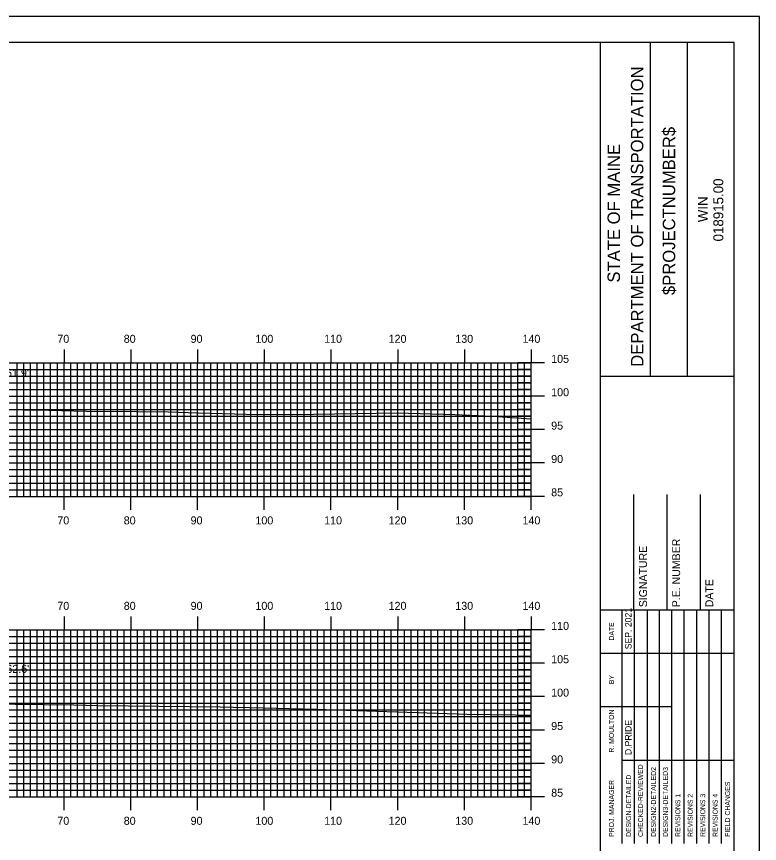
# Model space of a CAD drawing. Extents: x 1775170 to 1775514, y 442591 to 442811.
# Drawn here: x 1775399.1 to 1775510.4, y 442686.7 to 442810.5 of the extents above; entities that cross this region are included whole.
import ezdxf

# ---------------------------------------------------------------- set-up
doc = ezdxf.new("R2010")
doc.units = 0
for name, color, linetype in [('BORDER', 7, 'Continuous'), ('D_Text_Standard', 7, 'Continuous'), ('H_V ANNOTATION', 7, 'Continuous'), ('MAJOR', 7, 'Continuous'), ('MINOR', 7, 'Continuous'), ('PLOT BOUNDARY', 7, 'Continuous'), ('S_Roadway_Centerline', 7, 'Continuous')]:
    doc.layers.add(name, color=color, linetype=linetype)

msp = doc.modelspace()

# ---------------------------------------------------------------- linework, layer by layer
at = {"layer": 'BORDER'}
for p, q in [((1775486.6, 442596.67), (1775486.6, 442806.67)), ((1775494.06, 442756.66), (1775494.06, 442806.66)), ((1775499.65, 442756.66), (1775499.65, 442806.66)), ((1775486.6, 442756.65), (1775506.6, 442756.65)), ((1775491.6, 442721.67), (1775491.6, 442738.97)), ((1775496.6, 442721.67), (1775496.6, 442738.97)), ((1775501.6, 442721.67), (1775501.6, 442738.97)), ((1775486.6, 442721.67), (1775506.6, 442721.67))]:
    msp.add_line(p, q, dxfattribs=at)
msp.add_lwpolyline([(1775186.6, 442596.67), (1775506.6, 442596.67), (1775506.6, 442806.67), (1775186.6, 442806.67)], close=True, dxfattribs=at)
for points in [[(1775489.83, 442715.17), (1775489.83, 442721.67)], [(1775491.69, 442686.68), (1775491.69, 442721.67)], [(1775493.56, 442721.67), (1775493.56, 442686.68)], [(1775495.42, 442686.68), (1775495.42, 442721.67)], [(1775497.28, 442686.68), (1775497.28, 442721.67)], [(1775499.15, 442686.68), (1775499.15, 442721.67)], [(1775501.01, 442686.68), (1775501.01, 442721.67)], [(1775502.87, 442686.68), (1775502.87, 442721.67)], [(1775504.74, 442686.68), (1775504.74, 442721.67)], [(1775489.83, 442686.68), (1775489.83, 442720.26)], [(1775486.6, 442715.17), (1775506.6, 442715.17)], [(1775486.6, 442707.17), (1775489.83, 442707.17)], [(1775489.83, 442707.17), (1775497.28, 442707.17)], [(1775489.83, 442699.17), (1775506.6, 442699.17)]]:
    msp.add_lwpolyline(points, dxfattribs=at)
at = {"layer": 'MAJOR'}
for p, q in [((1775406.2, 442760.67), (1775406.2, 442758.67)), ((1775416.2, 442760.67), (1775416.2, 442758.67)), ((1775426.2, 442760.67), (1775426.2, 442758.67)), ((1775436.2, 442760.67), (1775436.2, 442758.67)), ((1775446.2, 442760.67), (1775446.2, 442758.67)), ((1775456.2, 442760.67), (1775456.2, 442758.67)), ((1775466.2, 442760.67), (1775466.2, 442758.67)), ((1775476.2, 442760.67), (1775476.2, 442758.67)), ((1775196.2, 442758.67), (1775476.2, 442758.67)), ((1775196.2, 442758.67), (1775476.2, 442758.67)), ((1775406.2, 442738.67), (1775406.2, 442758.67)), ((1775416.2, 442738.67), (1775416.2, 442758.67)), ((1775426.2, 442738.67), (1775426.2, 442758.67)), ((1775436.2, 442738.67), (1775436.2, 442758.67)), ((1775446.2, 442738.67), (1775446.2, 442758.67)), ((1775456.2, 442738.67), (1775456.2, 442758.67)), ((1775466.2, 442738.67), (1775466.2, 442758.67)), ((1775478.2, 442758.67), (1775474.19, 442758.67)), ((1775476.2, 442738.67), (1775476.2, 442758.67)), ((1775476.2, 442738.67), (1775476.2, 442758.67)), ((1775196.2, 442753.67), (1775476.2, 442753.67)), ((1775478.2, 442753.67), (1775474.19, 442753.67)), ((1775196.2, 442748.67), (1775476.2, 442748.67)), ((1775478.2, 442748.67), (1775474.19, 442748.67)), ((1775196.2, 442743.67), (1775476.2, 442743.67)), ((1775478.2, 442743.67), (1775474.19, 442743.67)), ((1775196.2, 442738.67), (1775476.2, 442738.67)), ((1775196.2, 442738.67), (1775476.2, 442738.67)), ((1775406.2, 442736.66), (1775406.2, 442738.67)), ((1775416.2, 442736.66), (1775416.2, 442738.67)), ((1775426.2, 442736.66), (1775426.2, 442738.67)), ((1775436.2, 442736.66), (1775436.2, 442738.67)), ((1775446.2, 442736.66), (1775446.2, 442738.67)), ((1775456.2, 442736.66), (1775456.2, 442738.67)), ((1775466.2, 442736.66), (1775466.2, 442738.67)), ((1775478.2, 442738.67), (1775474.19, 442738.67)), ((1775476.2, 442736.66), (1775476.2, 442738.67)), ((1775406.2, 442720.67), (1775406.2, 442718.67)), ((1775416.2, 442720.67), (1775416.2, 442718.67)), ((1775426.2, 442720.67), (1775426.2, 442718.67)), ((1775436.2, 442720.67), (1775436.2, 442718.67)), ((1775446.2, 442720.67), (1775446.2, 442718.67)), ((1775456.2, 442720.67), (1775456.2, 442718.67)), ((1775466.2, 442720.67), (1775466.2, 442718.67)), ((1775476.2, 442720.67), (1775476.2, 442718.67)), ((1775196.2, 442718.67), (1775476.2, 442718.67)), ((1775196.2, 442718.67), (1775476.2, 442718.67)), ((1775406.2, 442693.67), (1775406.2, 442718.67)), ((1775416.2, 442693.67), (1775416.2, 442718.67)), ((1775426.2, 442693.67), (1775426.2, 442718.67)), ((1775436.2, 442693.67), (1775436.2, 442718.67)), ((1775446.2, 442693.67), (1775446.2, 442718.67)), ((1775456.2, 442693.67), (1775456.2, 442718.67)), ((1775466.2, 442693.67), (1775466.2, 442718.67)), ((1775478.2, 442718.67), (1775474.19, 442718.67)), ((1775476.2, 442693.67), (1775476.2, 442718.67)), ((1775476.2, 442693.67), (1775476.2, 442718.67)), ((1775196.2, 442713.67), (1775476.2, 442713.67)), ((1775478.2, 442713.67), (1775474.19, 442713.67)), ((1775196.2, 442708.67), (1775476.2, 442708.67)), ((1775478.2, 442708.67), (1775474.19, 442708.67)), ((1775196.2, 442703.67), (1775476.2, 442703.67)), ((1775478.2, 442703.67), (1775474.19, 442703.67)), ((1775196.2, 442698.67), (1775476.2, 442698.67)), ((1775478.2, 442698.67), (1775474.19, 442698.67)), ((1775196.2, 442693.67), (1775476.2, 442693.67)), ((1775196.2, 442693.67), (1775476.2, 442693.67)), ((1775406.2, 442691.66), (1775406.2, 442693.67)), ((1775416.2, 442691.66), (1775416.2, 442693.67)), ((1775426.2, 442691.66), (1775426.2, 442693.67)), ((1775436.2, 442691.66), (1775436.2, 442693.67)), ((1775446.2, 442691.66), (1775446.2, 442693.67)), ((1775456.2, 442691.66), (1775456.2, 442693.67)), ((1775466.2, 442691.66), (1775466.2, 442693.67)), ((1775478.2, 442693.67), (1775474.19, 442693.67)), ((1775476.2, 442691.66), (1775476.2, 442693.67))]:
    msp.add_line(p, q, dxfattribs=at)
at = {"layer": 'MINOR'}
for p, q in [((1775399.2, 442738.67), (1775399.2, 442758.67)), ((1775400.2, 442738.67), (1775400.2, 442758.67)), ((1775401.2, 442738.67), (1775401.2, 442758.67)), ((1775402.2, 442738.67), (1775402.2, 442758.67)), ((1775403.2, 442738.67), (1775403.2, 442758.67)), ((1775404.2, 442738.67), (1775404.2, 442758.67)), ((1775405.2, 442738.67), (1775405.2, 442758.67)), ((1775407.2, 442738.67), (1775407.2, 442758.67)), ((1775408.2, 442738.67), (1775408.2, 442758.67)), ((1775409.2, 442738.67), (1775409.2, 442758.67)), ((1775410.2, 442738.67), (1775410.2, 442758.67)), ((1775411.2, 442738.67), (1775411.2, 442758.67)), ((1775412.2, 442738.67), (1775412.2, 442758.67)), ((1775413.2, 442738.67), (1775413.2, 442758.67)), ((1775414.2, 442738.67), (1775414.2, 442758.67)), ((1775415.2, 442738.67), (1775415.2, 442758.67)), ((1775417.2, 442738.67), (1775417.2, 442758.67)), ((1775418.2, 442738.67), (1775418.2, 442758.67)), ((1775419.2, 442738.67), (1775419.2, 442758.67)), ((1775420.2, 442738.67), (1775420.2, 442758.67)), ((1775421.2, 442738.67), (1775421.2, 442758.67)), ((1775422.2, 442738.67), (1775422.2, 442758.67)), ((1775423.2, 442738.67), (1775423.2, 442758.67)), ((1775424.2, 442738.67), (1775424.2, 442758.67)), ((1775425.2, 442738.67), (1775425.2, 442758.67)), ((1775427.2, 442738.67), (1775427.2, 442758.67)), ((1775428.2, 442738.67), (1775428.2, 442758.67)), ((1775429.2, 442738.67), (1775429.2, 442758.67)), ((1775430.2, 442738.67), (1775430.2, 442758.67)), ((1775431.2, 442738.67), (1775431.2, 442758.67)), ((1775432.2, 442738.67), (1775432.2, 442758.67)), ((1775433.2, 442738.67), (1775433.2, 442758.67)), ((1775434.2, 442738.67), (1775434.2, 442758.67)), ((1775435.2, 442738.67), (1775435.2, 442758.67)), ((1775437.2, 442738.67), (1775437.2, 442758.67)), ((1775438.2, 442738.67), (1775438.2, 442758.67)), ((1775439.2, 442738.67), (1775439.2, 442758.67)), ((1775440.2, 442738.67), (1775440.2, 442758.67)), ((1775441.2, 442738.67), (1775441.2, 442758.67)), ((1775442.2, 442738.67), (1775442.2, 442758.67)), ((1775443.2, 442738.67), (1775443.2, 442758.67)), ((1775444.2, 442738.67), (1775444.2, 442758.67)), ((1775445.2, 442738.67), (1775445.2, 442758.67)), ((1775447.2, 442738.67), (1775447.2, 442758.67)), ((1775448.2, 442738.67), (1775448.2, 442758.67)), ((1775449.2, 442738.67), (1775449.2, 442758.67)), ((1775450.2, 442738.67), (1775450.2, 442758.67)), ((1775451.2, 442738.67), (1775451.2, 442758.67)), ((1775452.2, 442738.67), (1775452.2, 442758.67)), ((1775453.2, 442738.67), (1775453.2, 442758.67)), ((1775454.2, 442738.67), (1775454.2, 442758.67)), ((1775455.2, 442738.67), (1775455.2, 442758.67)), ((1775457.2, 442738.67), (1775457.2, 442758.67)), ((1775458.2, 442738.67), (1775458.2, 442758.67)), ((1775459.2, 442738.67), (1775459.2, 442758.67)), ((1775460.2, 442738.67), (1775460.2, 442758.67)), ((1775461.2, 442738.67), (1775461.2, 442758.67)), ((1775462.2, 442738.67), (1775462.2, 442758.67)), ((1775463.2, 442738.67), (1775463.2, 442758.67)), ((1775464.2, 442738.67), (1775464.2, 442758.67)), ((1775465.2, 442738.67), (1775465.2, 442758.67)), ((1775467.2, 442738.67), (1775467.2, 442758.67)), ((1775468.2, 442738.67), (1775468.2, 442758.67)), ((1775469.2, 442738.67), (1775469.2, 442758.67)), ((1775470.2, 442738.67), (1775470.2, 442758.67)), ((1775471.2, 442738.67), (1775471.2, 442758.67)), ((1775472.2, 442738.67), (1775472.2, 442758.67)), ((1775473.2, 442738.67), (1775473.2, 442758.67)), ((1775474.2, 442738.67), (1775474.2, 442758.67)), ((1775475.2, 442738.67), (1775475.2, 442758.67)), ((1775196.2, 442757.67), (1775476.2, 442757.67)), ((1775476.2, 442757.67), (1775474.19, 442757.67)), ((1775196.2, 442756.67), (1775476.2, 442756.67)), ((1775476.2, 442756.67), (1775474.19, 442756.67)), ((1775196.2, 442755.67), (1775476.2, 442755.67)), ((1775476.2, 442755.67), (1775474.19, 442755.67)), ((1775196.2, 442754.67), (1775476.2, 442754.67)), ((1775476.2, 442754.67), (1775474.19, 442754.67)), ((1775196.2, 442752.67), (1775476.2, 442752.67)), ((1775476.2, 442752.67), (1775474.19, 442752.67)), ((1775196.2, 442751.67), (1775476.2, 442751.67)), ((1775476.2, 442751.67), (1775474.19, 442751.67)), ((1775196.2, 442750.67), (1775476.2, 442750.67)), ((1775476.2, 442750.67), (1775474.19, 442750.67)), ((1775196.2, 442749.67), (1775476.2, 442749.67)), ((1775476.2, 442749.67), (1775474.19, 442749.67)), ((1775196.2, 442747.67), (1775476.2, 442747.67)), ((1775476.2, 442747.67), (1775474.19, 442747.67)), ((1775196.2, 442746.67), (1775476.2, 442746.67)), ((1775476.2, 442746.67), (1775474.19, 442746.67)), ((1775196.2, 442745.67), (1775476.2, 442745.67)), ((1775476.2, 442745.67), (1775474.19, 442745.67)), ((1775196.2, 442744.67), (1775476.2, 442744.67)), ((1775476.2, 442744.67), (1775474.19, 442744.67)), ((1775196.2, 442742.67), (1775476.2, 442742.67)), ((1775476.2, 442742.67), (1775474.19, 442742.67)), ((1775196.2, 442741.67), (1775476.2, 442741.67)), ((1775476.2, 442741.67), (1775474.19, 442741.67)), ((1775196.2, 442740.67), (1775476.2, 442740.67)), ((1775476.2, 442740.67), (1775474.19, 442740.67)), ((1775196.2, 442739.67), (1775476.2, 442739.67)), ((1775476.2, 442739.67), (1775474.19, 442739.67)), ((1775399.2, 442693.67), (1775399.2, 442718.67)), ((1775400.2, 442693.67), (1775400.2, 442718.67)), ((1775401.2, 442693.67), (1775401.2, 442718.67)), ((1775402.2, 442693.67), (1775402.2, 442718.67)), ((1775403.2, 442693.67), (1775403.2, 442718.67)), ((1775404.2, 442693.67), (1775404.2, 442718.67)), ((1775405.2, 442693.67), (1775405.2, 442718.67)), ((1775407.2, 442693.67), (1775407.2, 442718.67)), ((1775408.2, 442693.67), (1775408.2, 442718.67)), ((1775409.2, 442693.67), (1775409.2, 442718.67)), ((1775410.2, 442693.67), (1775410.2, 442718.67)), ((1775411.2, 442693.67), (1775411.2, 442718.67)), ((1775412.2, 442693.67), (1775412.2, 442718.67)), ((1775413.2, 442693.67), (1775413.2, 442718.67)), ((1775414.2, 442693.67), (1775414.2, 442718.67)), ((1775415.2, 442693.67), (1775415.2, 442718.67)), ((1775417.2, 442693.67), (1775417.2, 442718.67)), ((1775418.2, 442693.67), (1775418.2, 442718.67)), ((1775419.2, 442693.67), (1775419.2, 442718.67)), ((1775420.2, 442693.67), (1775420.2, 442718.67)), ((1775421.2, 442693.67), (1775421.2, 442718.67)), ((1775422.2, 442693.67), (1775422.2, 442718.67)), ((1775423.2, 442693.67), (1775423.2, 442718.67)), ((1775424.2, 442693.67), (1775424.2, 442718.67)), ((1775425.2, 442693.67), (1775425.2, 442718.67)), ((1775427.2, 442693.67), (1775427.2, 442718.67)), ((1775428.2, 442693.67), (1775428.2, 442718.67)), ((1775429.2, 442693.67), (1775429.2, 442718.67)), ((1775430.2, 442693.67), (1775430.2, 442718.67)), ((1775431.2, 442693.67), (1775431.2, 442718.67)), ((1775432.2, 442693.67), (1775432.2, 442718.67)), ((1775433.2, 442693.67), (1775433.2, 442718.67)), ((1775434.2, 442693.67), (1775434.2, 442718.67)), ((1775435.2, 442693.67), (1775435.2, 442718.67)), ((1775437.2, 442693.67), (1775437.2, 442718.67)), ((1775438.2, 442693.67), (1775438.2, 442718.67)), ((1775439.2, 442693.67), (1775439.2, 442718.67)), ((1775440.2, 442693.67), (1775440.2, 442718.67)), ((1775441.2, 442693.67), (1775441.2, 442718.67)), ((1775442.2, 442693.67), (1775442.2, 442718.67)), ((1775443.2, 442693.67), (1775443.2, 442718.67)), ((1775444.2, 442693.67), (1775444.2, 442718.67)), ((1775445.2, 442693.67), (1775445.2, 442718.67)), ((1775447.2, 442693.67), (1775447.2, 442718.67)), ((1775448.2, 442693.67), (1775448.2, 442718.67)), ((1775449.2, 442693.67), (1775449.2, 442718.67)), ((1775450.2, 442693.67), (1775450.2, 442718.67)), ((1775451.2, 442693.67), (1775451.2, 442718.67)), ((1775452.2, 442693.67), (1775452.2, 442718.67)), ((1775453.2, 442693.67), (1775453.2, 442718.67)), ((1775454.2, 442693.67), (1775454.2, 442718.67)), ((1775455.2, 442693.67), (1775455.2, 442718.67)), ((1775457.2, 442693.67), (1775457.2, 442718.67)), ((1775458.2, 442693.67), (1775458.2, 442718.67)), ((1775459.2, 442693.67), (1775459.2, 442718.67)), ((1775460.2, 442693.67), (1775460.2, 442718.67)), ((1775461.2, 442693.67), (1775461.2, 442718.67)), ((1775462.2, 442693.67), (1775462.2, 442718.67)), ((1775463.2, 442693.67), (1775463.2, 442718.67)), ((1775464.2, 442693.67), (1775464.2, 442718.67)), ((1775465.2, 442693.67), (1775465.2, 442718.67)), ((1775467.2, 442693.67), (1775467.2, 442718.67)), ((1775468.2, 442693.67), (1775468.2, 442718.67)), ((1775469.2, 442693.67), (1775469.2, 442718.67)), ((1775470.2, 442693.67), (1775470.2, 442718.67)), ((1775471.2, 442693.67), (1775471.2, 442718.67)), ((1775472.2, 442693.67), (1775472.2, 442718.67)), ((1775473.2, 442693.67), (1775473.2, 442718.67)), ((1775474.2, 442693.67), (1775474.2, 442718.67)), ((1775475.2, 442693.67), (1775475.2, 442718.67)), ((1775196.2, 442717.67), (1775476.2, 442717.67)), ((1775196.2, 442716.67), (1775476.2, 442716.67)), ((1775476.2, 442717.67), (1775474.19, 442717.67)), ((1775476.2, 442716.67), (1775474.19, 442716.67)), ((1775196.2, 442715.67), (1775476.2, 442715.67)), ((1775476.2, 442715.67), (1775474.19, 442715.67)), ((1775196.2, 442714.67), (1775476.2, 442714.67)), ((1775476.2, 442714.67), (1775474.19, 442714.67)), ((1775196.2, 442712.67), (1775476.2, 442712.67)), ((1775196.2, 442711.67), (1775476.2, 442711.67)), ((1775476.2, 442712.67), (1775474.19, 442712.67)), ((1775476.2, 442711.67), (1775474.19, 442711.67)), ((1775196.2, 442710.67), (1775476.2, 442710.67)), ((1775476.2, 442710.67), (1775474.19, 442710.67)), ((1775196.2, 442709.67), (1775476.2, 442709.67)), ((1775476.2, 442709.67), (1775474.19, 442709.67)), ((1775196.2, 442707.67), (1775476.2, 442707.67)), ((1775196.2, 442706.67), (1775476.2, 442706.67)), ((1775476.2, 442707.67), (1775474.19, 442707.67)), ((1775476.2, 442706.67), (1775474.19, 442706.67)), ((1775196.2, 442705.67), (1775476.2, 442705.67)), ((1775476.2, 442705.67), (1775474.19, 442705.67)), ((1775196.2, 442704.67), (1775476.2, 442704.67)), ((1775476.2, 442704.67), (1775474.19, 442704.67)), ((1775196.2, 442702.67), (1775476.2, 442702.67)), ((1775196.2, 442701.67), (1775476.2, 442701.67)), ((1775476.2, 442702.67), (1775474.19, 442702.67)), ((1775476.2, 442701.67), (1775474.19, 442701.67)), ((1775196.2, 442700.67), (1775476.2, 442700.67)), ((1775476.2, 442700.67), (1775474.19, 442700.67)), ((1775196.2, 442699.67), (1775476.2, 442699.67)), ((1775476.2, 442699.67), (1775474.19, 442699.67)), ((1775196.2, 442697.67), (1775476.2, 442697.67)), ((1775196.2, 442696.67), (1775476.2, 442696.67)), ((1775476.2, 442697.67), (1775474.19, 442697.67)), ((1775476.2, 442696.67), (1775474.19, 442696.67)), ((1775196.2, 442695.67), (1775476.2, 442695.67)), ((1775476.2, 442695.67), (1775474.19, 442695.67)), ((1775196.2, 442694.67), (1775476.2, 442694.67)), ((1775476.2, 442694.67), (1775474.19, 442694.67))]:
    msp.add_line(p, q, dxfattribs=at)
at = {"layer": 'PLOT BOUNDARY'}
msp.add_lwpolyline([(1775170.41, 442590.55), (1775510.41, 442590.55), (1775510.41, 442810.55), (1775170.41, 442810.55)], close=True, dxfattribs=at)
at = {"layer": 'S_Roadway_Centerline'}
for points in [[(1775392.41, 442751.75), (1775403.92, 442751.56), (1775409.58, 442751.41), (1775416.99, 442751.39), (1775421.87, 442751.31), (1775426.32, 442751.18), (1775433.54, 442751), (1775440.5, 442750.93), (1775456.06, 442751.18), (1775464.76, 442750.94), (1775468.09, 442750.8), (1775471.18, 442750.64), (1775476.2, 442750.27)], [(1775385.58, 442707.67), (1775407.68, 442707.44), (1775409.5, 442707.38), (1775411.28, 442707.36), (1775429.58, 442707.13), (1775431.55, 442707.08), (1775433.97, 442707.05), (1775443.99, 442706.77), (1775459.13, 442706.28), (1775466.6, 442706.03), (1775473.79, 442705.93), (1775476.2, 442705.87)]]:
    msp.add_lwpolyline(points, dxfattribs=at)

# ---------------------------------------------------------------- texts
at = {"layer": 'BORDER'}
for s, height, p in [('DEPARTMENT OF TRANSPORTATION', 1.8635, (1775493.01, 442758.08)), ('$PROJECTNUMBER$', 1.8635, (1775497.78, 442768.82)), ('STATE OF MAINE', 1.8635, (1775489.51, 442770.69)), ('018915.00', 1.491, (1775504.99, 442776.86)), ('WIN', 1.491, (1775502.67, 442779.73)), ('P.E. NUMBER', 1.1811, (1775498.52, 442722.06)), ('SIGNATURE', 1.181, (1775493.56, 442722.06)), ('DATE', 1.181, (1775503.48, 442722.06)), ('SEP. 2021', 0.969, (1775491.24, 442715.76)), ('DATE', 0.743, (1775488.61, 442717.08)), ('BY', 0.743, (1775488.61, 442710.54)), ('R. MOULTON', 0.745, (1775488.61, 442700.28)), ('D.PRIDE', 0.969, (1775491.24, 442699.92)), ('CHECKED-REVIEWED', 0.7455, (1775492.96, 442687.65)), ('DESIGN2-DETAILED2', 0.7455, (1775494.9, 442687.65)), ('DESIGN3-DETAILED3', 0.7455, (1775496.69, 442687.65)), ('PROJ. MANAGER', 0.7455, (1775488.61, 442687.65)), ('DESIGN-DETAILED', 0.7455, (1775491.17, 442687.65)), ('FIELD CHANGES', 0.7455, (1775506, 442687.65)), ('REVISIONS 1', 0.7455, (1775498.55, 442687.65)), ('REVISIONS 2', 0.7455, (1775500.41, 442687.65)), ('REVISIONS 3', 0.7455, (1775502.28, 442687.65)), ('REVISIONS 4', 0.7455, (1775504.14, 442687.65))]:
    msp.add_text(s, height=height, rotation=90, dxfattribs=at).set_placement(p)
at = {"layer": 'D_Text_Standard'}
for s, p in [("61.9'", (1775397.51, 442756.56)), ("62.6'", (1775397.56, 442712.23))]:
    msp.add_text(s, height=1.2, dxfattribs=at).set_placement(p)
at = {"layer": 'H_V ANNOTATION'}
for s, p in [('70', (1775405.2, 442761.67)), ('80', (1775415.15, 442761.67)), ('90', (1775425.17, 442761.67)), ('100', (1775434.88, 442761.67)), ('110', (1775445.18, 442761.67)), ('120', (1775454.84, 442761.67)), ('130', (1775464.83, 442761.67)), ('140', (1775474.9, 442761.67)), ('105', (1775479.2, 442758.67)), ('100', (1775479.2, 442753.67)), ('95', (1775479.2, 442748.67)), ('90', (1775479.2, 442743.67)), ('85', (1775479.2, 442738.67)), ('70', (1775405.2, 442734.47)), ('80', (1775415.15, 442734.47)), ('90', (1775425.17, 442734.47)), ('100', (1775434.88, 442734.47)), ('110', (1775445.18, 442734.47)), ('120', (1775454.84, 442734.47)), ('130', (1775464.83, 442734.47)), ('140', (1775474.9, 442734.47)), ('70', (1775405.2, 442721.67)), ('80', (1775415.15, 442721.67)), ('90', (1775425.17, 442721.67)), ('100', (1775434.88, 442721.67)), ('110', (1775445.18, 442721.67)), ('120', (1775454.84, 442721.67)), ('130', (1775464.83, 442721.67)), ('140', (1775474.9, 442721.67)), ('110', (1775479.2, 442718.67)), ('105', (1775479.2, 442713.67)), ('100', (1775479.2, 442708.67)), ('95', (1775479.2, 442703.67)), ('90', (1775479.2, 442698.67)), ('85', (1775479.2, 442693.67)), ('70', (1775405.2, 442689.47)), ('80', (1775415.15, 442689.47)), ('90', (1775425.17, 442689.47)), ('100', (1775434.88, 442689.47)), ('110', (1775445.18, 442689.47)), ('120', (1775454.84, 442689.47)), ('130', (1775464.83, 442689.47)), ('140', (1775474.9, 442689.47))]:
    msp.add_text(s, height=1.2, dxfattribs=at).set_placement(p)

doc.saveas('drawing.dxf')
